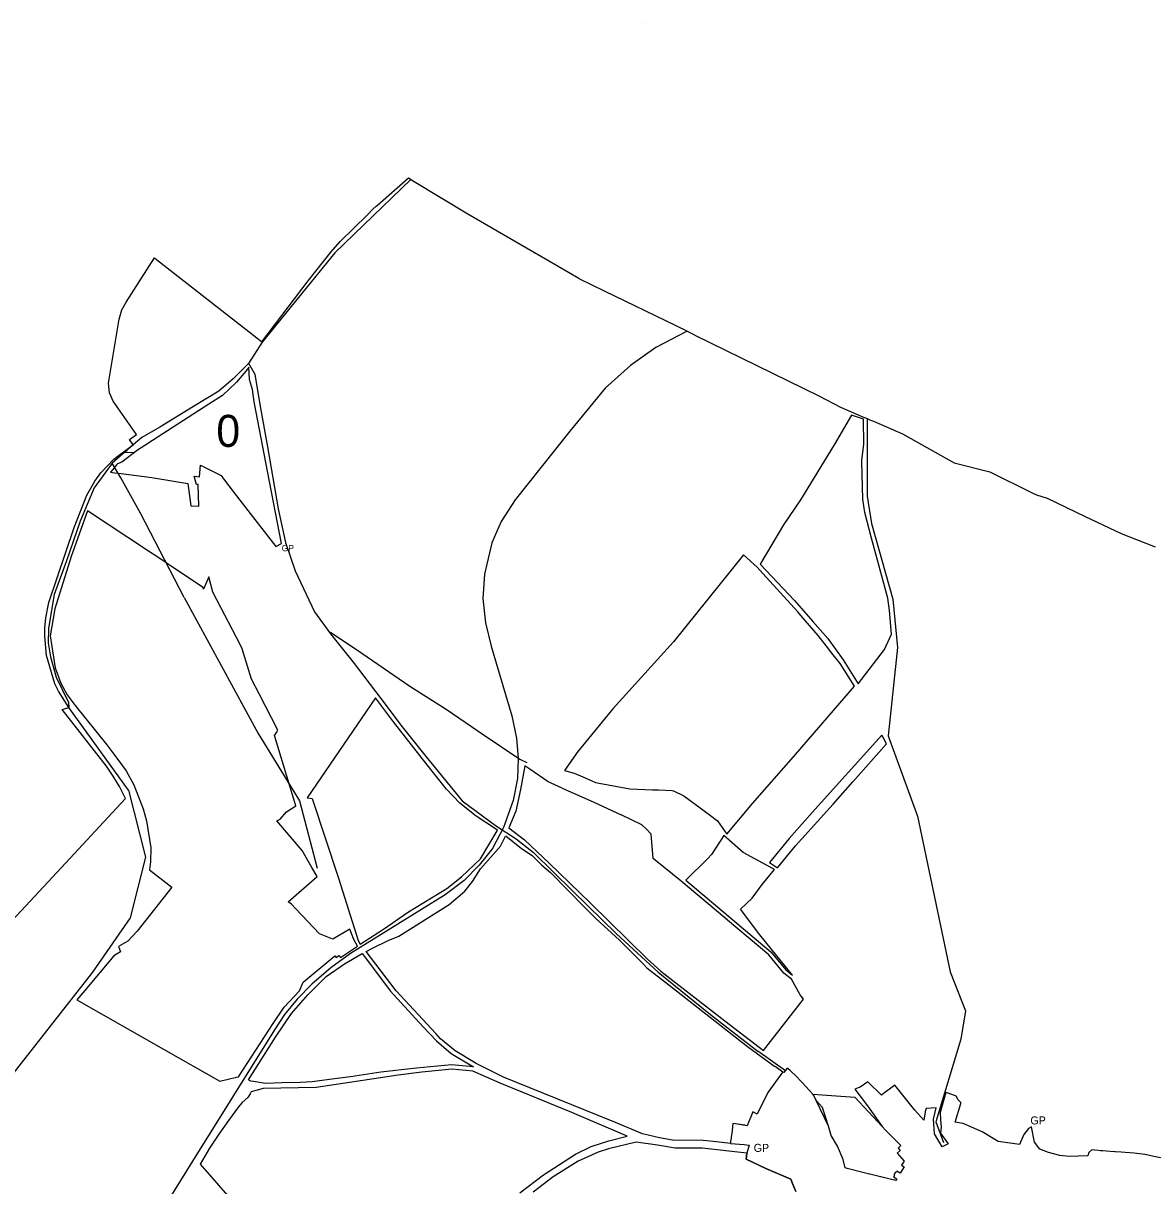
# Model space of a CAD drawing. Extents: x -584576 to -579722, y -1113169 to -1110375.
# Drawn here: x -583298 to -581887, y -1111827 to -1110375 of the extents above; entities that cross this region are included whole.
import ezdxf

# ---------------------------------------------------------------- set-up
doc = ezdxf.new("R2010")
doc.units = 0
for name, color, linetype in [('CESTY', 7, 'Continuous'), ('GRA_ZV', 7, 'Continuous'), ('Level 255', 7, 'Continuous'), ('OVNE_PRE', 7, 'Continuous'), ('OVNE_SET', 7, 'Continuous'), ('OVNI_PRE', 7, 'Continuous'), ('OVNI_SET', 7, 'Continuous'), ('VODA', 7, 'Continuous')]:
    doc.layers.add(name, color=color, linetype=linetype)

msp = doc.modelspace()

# ---------------------------------------------------------------- linework, layer by layer
at = {"layer": 'CESTY'}
for points in [[(-582468.3, -1110759.2), (-582507.4, -1110779.5), (-582539, -1110802), (-582570.7, -1110830.3), (-582614.7, -1110884.3), (-582683, -1110970.1), (-582700.7, -1110997.1), (-582712.1, -1111023.6), (-582721.3, -1111062.9), (-582723.5, -1111093.1), (-582720.2, -1111123.6), (-582713.1, -1111152.8), (-582687.2, -1111239.6), (-582681.3, -1111267.8), (-582679.5, -1111293.2), (-582680.3, -1111317.9), (-582685.6, -1111345.4), (-582697.6, -1111379.3), (-582711.3, -1111405.4), (-582728.2, -1111426.4), (-582746.7, -1111445.5), (-582770.6, -1111463.3), (-582888.9, -1111536.8), (-582913.6, -1111554.6), (-582937.2, -1111574.8), (-582955.7, -1111593.9), (-582971.4, -1111612.9), (-582984, -1111632), (-583086.3, -1111796.1), (-583161.2, -1111917)], [(-582243.2, -1110869.4), (-582243.2, -1110965.4), (-582238, -1110999.4), (-582211.4, -1111094), (-582205.5, -1111154.6), (-582217.3, -1111264.7), (-582180.4, -1111365.1), (-582139.7, -1111559.5), (-582120.5, -1111608.2), (-582126.4, -1111643.7), (-582157.5, -1111747.1), (-582147.9, -1111773)]]:
    msp.add_lwpolyline(points, dxfattribs=at)
at = {"layer": 'GRA_ZV'}
for p, q in [((-582691, -1111379.9), (-582691, -1111379.9)), ((-582220.5, -1111757.3), (-582220.5, -1111757.3))]:
    msp.add_line(p, q, dxfattribs=at)
for points in [[(-582262.9, -1110864), (-582284.5, -1110901.4), (-582326.8, -1110969.9), (-582347.8, -1111001.1), (-582377.1, -1111050.1), (-582334, -1111095.7), (-582311.3, -1111122), (-582292.7, -1111143.1), (-582273.4, -1111169.8), (-582254.7, -1111199.8), (-582221.7, -1111156.7), (-582213, -1111137.6), (-582215.4, -1111108.3), (-582217.5, -1111092.7), (-582238.1, -1111018), (-582246.4, -1110985.6), (-582248.6, -1110969.1), (-582250, -1110922.9), (-582250.1, -1110920.3), (-582247.4, -1110901), (-582247.9, -1110869.3), (-582262.9, -1110864)], [(-582958.5, -1111348.1), (-582964.3, -1111328.7), (-582983.7, -1111264.3), (-582981.5, -1111260.6), (-582979.5, -1111257.8), (-583002.9, -1111212.2), (-583012.5, -1111194), (-583024.1, -1111156), (-583026.2, -1111151.6), (-583060.7, -1111085.4), (-583065.7, -1111066.3), (-583072.4, -1111081.5), (-583072.8, -1111079.4), (-583117.4, -1111049.8), (-583118.3, -1111049.2), (-583128, -1111042.9), (-583128.5, -1111042.5), (-583141.4, -1111034.1), (-583217.5, -1110983.8), (-583235.9, -1111035), (-583238, -1111040.7), (-583258.3, -1111106.2), (-583263.9, -1111139.9), (-583258, -1111179.7), (-583250.7, -1111198.8), (-583242.7, -1111213.7), (-583233, -1111227), (-583193.1, -1111275.8), (-583180.6, -1111292.7), (-583169, -1111308.5), (-583159.7, -1111326.1), (-583147.8, -1111356.1), (-583143.8, -1111370.8), (-583138.5, -1111404.8), (-583138.9, -1111422), (-583140, -1111432), (-583112.2, -1111453.8)], [(-582398, -1111038.6), (-582485.4, -1111147.4), (-582561.3, -1111231.2), (-582605, -1111284.3), (-582621.6, -1111307.9), (-582609.4, -1111311.3), (-582598.8, -1111316), (-582588.3, -1111320.5), (-582582.7, -1111323.1), (-582540, -1111330.9), (-582511.6, -1111332.1), (-582504.2, -1111332.4), (-582486.8, -1111332.9), (-582485.4, -1111333.6), (-582472.4, -1111339.8), (-582452.2, -1111354.9), (-582445.4, -1111359.7), (-582439.2, -1111364.4), (-582430.5, -1111371.1), (-582418.5, -1111387.4), (-582386.6, -1111349.1), (-582335.5, -1111291.1), (-582259, -1111202.6), (-582277.1, -1111174.2), (-582287.4, -1111161.4), (-582294, -1111152.8), (-582304.7, -1111139.6), (-582315.5, -1111126.9), (-582326.2, -1111114.3), (-582330.2, -1111109.8), (-582373.8, -1111062), (-582380.6, -1111053.9), (-582398, -1111038.6)], [(-582705.4, -1111382.6), (-582731.7, -1111365.1), (-582752.1, -1111348.7), (-582768.8, -1111331.4), (-582783.3, -1111312.9), (-582794.7, -1111298.9), (-582835.1, -1111247.3), (-582857.7, -1111217.2), (-582942.9, -1111342.3), (-582936.7, -1111342.9), (-582903.9, -1111442.7), (-582879.1, -1111520.3), (-582876.8, -1111525.1), (-582847.7, -1111506.2), (-582816.3, -1111484.7), (-582768.5, -1111455.5), (-582750.1, -1111441.1), (-582726.4, -1111418.6), (-582705.7, -1111383.3), (-582705.4, -1111382.6)], [(-582365.5, -1111423), (-582355.2, -1111429.6), (-582332.8, -1111402.1), (-582285.7, -1111350.2), (-582261.3, -1111322.1), (-582219.4, -1111274.8), (-582224, -1111266.1), (-582225.1, -1111264.1), (-582312.2, -1111360.7), (-582340.8, -1111393), (-582365.5, -1111423)], [(-582664.9, -1111306.5), (-582671, -1111302.3), (-582676.6, -1111332)], [(-582624.4, -1111330), (-582638.2, -1111324), (-582641.9, -1111322.4), (-582664.9, -1111306.5)], [(-582676.6, -1111332), (-582682.3, -1111358.7), (-582691, -1111379.9)], [(-582624.4, -1111330), (-582585.6, -1111347.2), (-582550.7, -1111363.4)], [(-582980.9, -1111370.9), (-582976.8, -1111368.9), (-582969, -1111359.8), (-582957.2, -1111352.4), (-582958.5, -1111348.1)], [(-582880.2, -1111527.4), (-582884.9, -1111519), (-582889.5, -1111506.4), (-582910.9, -1111518.8), (-582927.8, -1111512), (-582957.3, -1111480.7), (-582962.5, -1111475.1), (-582966.8, -1111472.1), (-582930.4, -1111440.5), (-582937.2, -1111429.1), (-582949.2, -1111408.2), (-582980.9, -1111370.9)], [(-582517.8, -1111543.8), (-582501.1, -1111558.6), (-582482.3, -1111573.2), (-582421.2, -1111620.6), (-582373, -1111658), (-582323.1, -1111593.7), (-582327, -1111588.5), (-582338, -1111568.8), (-582347.5, -1111561.4), (-582366.4, -1111538.4), (-582417.8, -1111495), (-582421.1, -1111492.2), (-582475.9, -1111446.2), (-582508.1, -1111419.9), (-582510.6, -1111418), (-582513.2, -1111387.5), (-582519.2, -1111381.5), (-582524.9, -1111375.8), (-582550.7, -1111363.4)], [(-582502.8, -1111767.1), (-582524.1, -1111761.9), (-582557.6, -1111747.8), (-582579.6, -1111738.9), (-582697.8, -1111691.3), (-582731.9, -1111674.2), (-582758, -1111658.3), (-582776.3, -1111643.1), (-582782.3, -1111636.5), (-582831.9, -1111583.3), (-582869.2, -1111534.1), (-582868.6, -1111533.8), (-582861.4, -1111530.1), (-582842, -1111520.3), (-582828.5, -1111514.9), (-582765.6, -1111475.5), (-582746.2, -1111459), (-582736.5, -1111446.8), (-582726.5, -1111430.8), (-582701.6, -1111402.4), (-582695.1, -1111389.9)], [(-582694.9, -1111389.6), (-582675.1, -1111405.6), (-582661.7, -1111414.4), (-582649.8, -1111426.5), (-582639.2, -1111435.7), (-582596, -1111479.1), (-582582.3, -1111493), (-582552.8, -1111520.2), (-582523.3, -1111549.7), (-582518.5, -1111554.4), (-582491.3, -1111575.9), (-582439.1, -1111616.8), (-582392.9, -1111652.9), (-582358.7, -1111677.9), (-582358.5, -1111677.6), (-582348.9, -1111684.4)], [(-582691, -1111379.9), (-582671.5, -1111394.5), (-582640.5, -1111424), (-582589.5, -1111473.4), (-582517.8, -1111543.8)], [(-582470.1, -1111445.2), (-582363.2, -1111535.1), (-582344.8, -1111556.9), (-582336.6, -1111563.9), (-582377.5, -1111513.4), (-582401.5, -1111481.4), (-582387.2, -1111467.5), (-582374.4, -1111450.6), (-582359.1, -1111431.7), (-582369, -1111426.4), (-582398.2, -1111410.4), (-582422.5, -1111389.2), (-582437.9, -1111413.2), (-582442.5, -1111417.8), (-582470.1, -1111445.2)], [(-583112.2, -1111453.8), (-583155.2, -1111508.6), (-583167.2, -1111521.2), (-583178.9, -1111527.9), (-583176.3, -1111534.8), (-583184.4, -1111539.5), (-583220.9, -1111582.8), (-583230.9, -1111594.6), (-583227.8, -1111596.2), (-583122.5, -1111656.4), (-583052, -1111696.1), (-583031.4, -1111691), (-583028.7, -1111690.7), (-582985.5, -1111624.1), (-582971.9, -1111603.8), (-582952.4, -1111583.2), (-582948.2, -1111572.7), (-582908.6, -1111539.5), (-582906.8, -1111541.8), (-582903.5, -1111539.1), (-582901.5, -1111541.6), (-582880.2, -1111527.4)], [(-582735.3, -1111678.4), (-582762.8, -1111675.6), (-582806.5, -1111679.8), (-582850.9, -1111685.1), (-582888.9, -1111690.6), (-582908.7, -1111693.4), (-582936.8, -1111697.1), (-582951.9, -1111697.9), (-582974.7, -1111698.4), (-582995, -1111699), (-583010.2, -1111696.8), (-583013.4, -1111696.1), (-583015.1, -1111695.2), (-583016.3, -1111694.4), (-582982.5, -1111641.3), (-582962.6, -1111611.6), (-582942.3, -1111588.2), (-582919.3, -1111565.6), (-582896.3, -1111549.8), (-582874.3, -1111536.7), (-582872.8, -1111538.7), (-582839.1, -1111583.5), (-582798.4, -1111627.7), (-582781.4, -1111645.8), (-582763.1, -1111661.6), (-582735.3, -1111678.4)], [(-582701.8, -1111698.6), (-582735.9, -1111683.8), (-582762.2, -1111681.1), (-582799.6, -1111684.8), (-582829.4, -1111688.6), (-582873.5, -1111695.3), (-582931.9, -1111704.1), (-582997.9, -1111705.4)], [(-582348.9, -1111684.4), (-582367.6, -1111710.5), (-582380.9, -1111737.2), (-582386.2, -1111734.5), (-582393.4, -1111751.8)], [(-582997.9, -1111705.4), (-583013, -1111709.3), (-583014.1, -1111711.9), (-583017.3, -1111716.7), (-583024.3, -1111722.8), (-583028.7, -1111728.4), (-583041.2, -1111745.2), (-583053.3, -1111762.4), (-583064.9, -1111779.8), (-583076.7, -1111799.7), (-582959.4, -1111934.2)], [(-582677.4, -1111835.6), (-582647.7, -1111813), (-582607.9, -1111787.3), (-582588.1, -1111777.8), (-582566, -1111770.6), (-582543.2, -1111764.9), (-582612.3, -1111735.2), (-582701.8, -1111698.6)], [(-582311.4, -1111712.3), (-582258.8, -1111716), (-582224.6, -1111752.7)], [(-582224.6, -1111752.7), (-582220.5, -1111757.3), (-582201.5, -1111776.6), (-582204.7, -1111779.7), (-582202, -1111782.7), (-582206, -1111786.3), (-582197.1, -1111796), (-582200.5, -1111801.3), (-582197.2, -1111803.4), (-582202.1, -1111811.3), (-582206.2, -1111808.7), (-582207.1, -1111810.3), (-582207.8, -1111809.9), (-582209.9, -1111813.3), (-582209.2, -1111813.7), (-582210.3, -1111815.5), (-582206.3, -1111818), (-582207.7, -1111820.4), (-582247, -1111810.6), (-582268.4, -1111805.3), (-582271, -1111804.5), (-582273.3, -1111794), (-582280.5, -1111777.2), (-582288.4, -1111764), (-582291.8, -1111752.5), (-582299, -1111728.9), (-582307, -1111720.2), (-582310, -1111714), (-582311.4, -1111712.3)], [(-582411, -1111748.9), (-582411.5, -1111752.9), (-582412.2, -1111758.2), (-582413.4, -1111766.7), (-582414, -1111772), (-582414.3, -1111773.9), (-582431.5, -1111771.8), (-582448.2, -1111770.4), (-582486.7, -1111769.7), (-582502.8, -1111767.1)], [(-582393.4, -1111751.8), (-582408, -1111749.4), (-582411, -1111748.9)], [(-582449.4, -1111779.8), (-582483.4, -1111780), (-582505.2, -1111776.2), (-582532.1, -1111772.3), (-582566.4, -1111780.7), (-582579.4, -1111784.7), (-582604.3, -1111796.3), (-582635.5, -1111815.8), (-582660.5, -1111834.8)], [(-582332.6, -1111834.1), (-582336.5, -1111824), (-582338.7, -1111818.5), (-582369.8, -1111805.2), (-582394.5, -1111793.8), (-582393.9, -1111786), (-582449.4, -1111779.8)]]:
    msp.add_lwpolyline(points, dxfattribs=at)
at = {"layer": 'Level 255'}
msp.add_line((-582660.9, -1110659.8), (-582655.3, -1110663.1), dxfattribs=at)
at = {"layer": 'OVNE_PRE'}
for p, q in [((-582816.5, -1110567.7), (-582809.2, -1110572.3)), ((-583006, -1110767.5), (-582999.5, -1110772.4)), ((-582343.4, -1111679.8), (-582343.4, -1111679.8))]:
    msp.add_line(p, q, dxfattribs=at)
for points in [[(-582999.5, -1110772.4), (-582941.9, -1110696.3), (-582913.2, -1110660.1), (-582901.9, -1110647.3), (-582867.5, -1110614), (-582860.9, -1110606.8), (-582856.7, -1110603.2), (-582855.3, -1110601.9), (-582816.5, -1110567.7)], [(-582809.2, -1110572.3), (-582742.4, -1110612.8), (-582660.9, -1110659.8)], [(-583160.2, -1110901.2), (-583164.8, -1110894.4), (-583156.1, -1110888.3), (-583185.2, -1110846.5), (-583190, -1110836.2), (-583191.3, -1110824.3), (-583177.8, -1110744.4), (-583174.4, -1110732.5), (-583169.3, -1110723), (-583133.6, -1110667.7)], [(-582603.6, -1110693.1), (-582602.6, -1110693.7), (-582572.1, -1110708.9)], [(-582572.1, -1110708.9), (-582482.6, -1110752.3), (-582474.1, -1110756.3), (-582473.6, -1110756.5), (-582467.5, -1110759.6), (-582459.3, -1110763.8), (-582458.5, -1110764.2), (-582303.6, -1110840.2), (-582276.6, -1110854.2), (-582248, -1110866.5), (-582244.3, -1110868.1), (-582239.3, -1110870.2), (-582235.6, -1110871.8), (-582199.3, -1110887.4), (-582134.7, -1110923.9), (-582090.1, -1110935.1), (-582036.6, -1110961.5), (-582031.9, -1110963.8), (-582018.6, -1110967.9), (-581971.2, -1110990.8), (-581926, -1111011.8), (-581883.7, -1111028.7)], [(-583011.3, -1110832.1), (-583015, -1110819.4), (-583015.9, -1110804.3)], [(-583240.6, -1111229.4), (-583253.6, -1111208.8), (-583258.1, -1111199.9), (-583268.7, -1111164.4), (-583270.8, -1111140.4), (-583270.6, -1111130.1), (-583269.5, -1111117.2), (-583265.8, -1111098.3), (-583234.2, -1111004.5), (-583218.1, -1110963.9), (-583208.4, -1110946.5), (-583200.8, -1110936.4), (-583184.6, -1110919.1), (-583177.3, -1110913.7), (-583160.2, -1110901.2)], [(-583180.9, -1111322.5), (-583185.4, -1111315.2), (-583193.9, -1111302.8), (-583248.9, -1111231.7), (-583240.6, -1111229.4)], [(-583170.1, -1111343.2), (-583170.8, -1111341.4), (-583177.5, -1111328), (-583178.8, -1111325.9), (-583180.9, -1111322.5)], [(-583891.8, -1112051.5), (-583740.7, -1111942.5), (-583688.5, -1111904.6), (-583675.7, -1111894.8), (-583666.2, -1111885.1), (-583600.7, -1111808.6), (-583566.2, -1111771.3), (-583537.4, -1111740.1), (-583451.5, -1111647.2), (-583441.4, -1111636.3), (-583367.8, -1111556.5), (-583325, -1111510.2), (-583316.9, -1111501.4), (-583239, -1111417.4), (-583191.9, -1111366.6), (-583170.1, -1111343.2)]]:
    msp.add_lwpolyline(points, dxfattribs=at)
at = {"layer": 'OVNE_SET'}
for p, q in [((-583009.1, -1110847.4), (-583011.3, -1110832.1)), ((-582252.3, -1111703.6), (-582252.3, -1111703.6))]:
    msp.add_line(p, q, dxfattribs=at)
for points in [[(-582660.9, -1110659.8), (-582657.9, -1110661.6), (-582655.3, -1110663.1), (-582603.6, -1110693.1)], [(-583133.6, -1110667.7), (-583131.4, -1110669.5), (-583006, -1110767.5)], [(-583015.9, -1110804.3), (-583017.7, -1110806.7), (-583031.4, -1110823.1), (-583048.7, -1110839.7), (-583065.9, -1110850.6), (-583136.1, -1110896), (-583145.8, -1110902), (-583155, -1110907.9), (-583174.7, -1110923), (-583179.8, -1110924.8), (-583181.1, -1110926.3), (-583185.7, -1110931.9), (-583188.6, -1110935.3)], [(-583188.6, -1110935.3), (-583183.6, -1110936), (-583175.5, -1110937.1), (-583137.1, -1110942), (-583092.1, -1110949.6), (-583088.2, -1110977.6), (-583078.3, -1110977.9), (-583079.1, -1110950.9), (-583081.3, -1110950.7), (-583084.2, -1110940.5), (-583077.5, -1110941.1), (-583076.1, -1110926.8), (-583050.5, -1110939.7), (-583047.7, -1110943.6), (-583034.2, -1110961), (-583014.2, -1110986.9), (-582982.2, -1111028.1), (-582974.9, -1111024.4), (-582990, -1110947.1), (-583009.1, -1110847.4)]]:
    msp.add_lwpolyline(points, dxfattribs=at)
at = {"layer": 'OVNI_PRE'}
for p, q in [((-582413.4, -1111766.7), (-582414, -1111772)), ((-582412.2, -1111758.2), (-582413.4, -1111766.7)), ((-581954.6, -1111783), (-581959, -1111782.4)), ((-581896.6, -1111787.7), (-581909.7, -1111786.2)), ((-582202.1, -1111811.3), (-582206.2, -1111808.7))]:
    msp.add_line(p, q, dxfattribs=at)
for points in [[(-582343.4, -1111679.8), (-582347.6, -1111685.4), (-582348.3, -1111684.9)], [(-582339.6, -1111682.7), (-582340.1, -1111682.3), (-582343.4, -1111679.8)], [(-582201.5, -1111776.6), (-582204.7, -1111779.7), (-582202, -1111782.7), (-582206, -1111786.3), (-582197.1, -1111796), (-582200.5, -1111801.3)], [(-581870.1, -1111793.2), (-581883.1, -1111790.6), (-581896.6, -1111787.7)], [(-582200.5, -1111801.3), (-582197.2, -1111803.4), (-582202.1, -1111811.3)]]:
    msp.add_lwpolyline(points, dxfattribs=at)
at = {"layer": 'OVNI_SET'}
for p, q in [((-582348.9, -1111684.4), (-582367.6, -1111710.5)), ((-582348.3, -1111684.9), (-582348.9, -1111684.4)), ((-582331.3, -1111690.9), (-582339.6, -1111682.7)), ((-582315.9, -1111707.3), (-582324.5, -1111697.7)), ((-582311.4, -1111712.3), (-582315.9, -1111707.3)), ((-582254.7, -1111704.6), (-582258.7, -1111706.2)), ((-582367.6, -1111710.5), (-582380.9, -1111737.2)), ((-582310, -1111714), (-582311.4, -1111712.3)), ((-582307, -1111720.2), (-582310, -1111714)), ((-582291.8, -1111752.5), (-582307, -1111720.2)), ((-582380.9, -1111737.2), (-582386.2, -1111734.5)), ((-582411.5, -1111752.9), (-582412.2, -1111758.2)), ((-582288.4, -1111764), (-582291.8, -1111752.5)), ((-582220.5, -1111757.3), (-582201.5, -1111776.6)), ((-582414, -1111772), (-582414.3, -1111773.9)), ((-582414.3, -1111773.9), (-582397.1, -1111775.5)), ((-581951.8, -1111783.2), (-581954.6, -1111783))]:
    msp.add_line(p, q, dxfattribs=at)
for points in [[(-582324.5, -1111697.7), (-582326.6, -1111695.6), (-582331.3, -1111690.9)], [(-582258.7, -1111706.2), (-582243.1, -1111727.2), (-582224.6, -1111752.7), (-582220.5, -1111757.3)], [(-582225.6, -1111713.8), (-582242.4, -1111697.1), (-582252.3, -1111703.6), (-582254.7, -1111704.6)], [(-582184, -1111732.6), (-582209, -1111701.3), (-582224.9, -1111713.3), (-582225.6, -1111713.8)], [(-582145.2, -1111710.4), (-582152.1, -1111735.3), (-582151.6, -1111744.3)], [(-582132, -1111714.8), (-582133.2, -1111714.3), (-582143.6, -1111710.9), (-582145.2, -1111710.4)], [(-582123.5, -1111749), (-582133.6, -1111747.2), (-582126.2, -1111724.2), (-582126.5, -1111722.9), (-582129.5, -1111719.6), (-582132, -1111714.8)], [(-582386.2, -1111734.5), (-582393.4, -1111751.8), (-582396.4, -1111751.3)], [(-582170.8, -1111734.3), (-582172.5, -1111744.9), (-582184, -1111732.6)], [(-582160.6, -1111743.8), (-582157.1, -1111729.6), (-582169.7, -1111730.4), (-582170, -1111731.4), (-582170.8, -1111734.3)], [(-582396.4, -1111751.3), (-582408, -1111749.4), (-582411, -1111748.9), (-582411.5, -1111752.9)], [(-582142.2, -1111774.6), (-582149.7, -1111778.1), (-582159.3, -1111762.1), (-582160.6, -1111743.8)], [(-582151.6, -1111744.3), (-582151, -1111753.5), (-582151.6, -1111761), (-582142.2, -1111774.6)], [(-582082, -1111770.3), (-582099.9, -1111759.4), (-582123.5, -1111749)], [(-582038.2, -1111753.3), (-582041.8, -1111755.2), (-582047.5, -1111762.9)], [(-582027.5, -1111781.2), (-582034.4, -1111772.5), (-582038.2, -1111753.3)], [(-582268.4, -1111805.3), (-582271, -1111804.5), (-582273.3, -1111794), (-582280.5, -1111777.2), (-582288.4, -1111764)], [(-582047.5, -1111762.9), (-582053.2, -1111775.1), (-582079.6, -1111771.5), (-582082, -1111770.3)], [(-582397.1, -1111775.5), (-582391, -1111776.2), (-582393.9, -1111786)], [(-581966.5, -1111785.1), (-581967.5, -1111789.4), (-581990.9, -1111790.2), (-582002.5, -1111789.2), (-582017, -1111785.2), (-582027.5, -1111781.2)], [(-581959, -1111782.4), (-581962.8, -1111782.1), (-581966.5, -1111785.1)], [(-582393.9, -1111786), (-582394.5, -1111793.8), (-582369.8, -1111805.2)], [(-581926.1, -1111785), (-581933.3, -1111784.5), (-581934.3, -1111784.4), (-581939.7, -1111784.1), (-581944.4, -1111783.7), (-581948.8, -1111783.4), (-581951.8, -1111783.2)], [(-581909.7, -1111786.2), (-581915.1, -1111785.8), (-581921.2, -1111785.4), (-581926.1, -1111785)], [(-582369.8, -1111805.2), (-582338.7, -1111818.5), (-582336.5, -1111824), (-582332.6, -1111834.1)], [(-582206.3, -1111818), (-582207.7, -1111820.4), (-582213, -1111819.1), (-582247, -1111810.6), (-582268.4, -1111805.3)], [(-582206.2, -1111808.7), (-582207.1, -1111810.3), (-582207.8, -1111809.9), (-582209.9, -1111813.3), (-582209.2, -1111813.7), (-582210.3, -1111815.5), (-582206.3, -1111818)]]:
    msp.add_lwpolyline(points, dxfattribs=at)
at = {"layer": 'VODA'}
for p, q in [((-582524.4, -1110374.5), (-582524.4, -1110374.5)), ((-582813, -1110569.5), (-582813, -1110569.5)), ((-583016.2, -1110799.2), (-583014.4, -1110803)), ((-583014.4, -1110803), (-583014.4, -1110803)), ((-583167.4, -1110910.4), (-583167.4, -1110910.4)), ((-583167.4, -1110910.4), (-583167.4, -1110910.4)), ((-583175.9, -1110942.4), (-583186.5, -1110924.3)), ((-583175.9, -1110942.4), (-583175.9, -1110942.4)), ((-583175.9, -1110942.4), (-583175.9, -1110942.4)), ((-583166.3, -1111332.7), (-583240.6, -1111229.4)), ((-582379.9, -1111658.3), (-582345.2, -1111682.7))]:
    msp.add_line(p, q, dxfattribs=at)
for points in [[(-582813, -1110569.5), (-582908.5, -1110661.3), (-582999.4, -1110772.8)], [(-582999.4, -1110772.8), (-583016.4, -1110799.7), (-583035.3, -1110818.6), (-583053.4, -1110834.1), (-583085.2, -1110853.3), (-583126.9, -1110879.2), (-583149.5, -1110892.1)], [(-583016.2, -1110799.2), (-583008.3, -1110813), (-583002, -1110850.7), (-582992.6, -1110903.9), (-582979.1, -1110981.1), (-582970.2, -1111023.2), (-582957.9, -1111058.7), (-582933.8, -1111109.7), (-582913.9, -1111137.4), (-582885.4, -1111172.9), (-582851.1, -1111218.1), (-582824.3, -1111253.4), (-582794.5, -1111291.1), (-582749.4, -1111345.9), (-582706.6, -1111377.7), (-582681.8, -1111393.4), (-582660.2, -1111410.4), (-582611.1, -1111459), (-582556.7, -1111512), (-582504.4, -1111560.2), (-582438.9, -1111613), (-582379.4, -1111659)], [(-583149.5, -1110892.1), (-583160.2, -1110901.2), (-583186.5, -1110924.3), (-583209.1, -1110954.8), (-583226.5, -1110996.4), (-583243.8, -1111046), (-583259.1, -1111088.3), (-583266, -1111130.3), (-583266.4, -1111148.6), (-583263.7, -1111165.9), (-583256.4, -1111191.3), (-583241.2, -1111223.2), (-583240.6, -1111229.4)], [(-583172.6, -1110910.2), (-583167.4, -1110910.4), (-583158.7, -1110910.7)], [(-583096.8, -1111091.8), (-583150.9, -1110987.6), (-583175.9, -1110942.4)], [(-583096.8, -1111091.8), (-583004.4, -1111261.7), (-582952.7, -1111345.9), (-582930.5, -1111430.2)], [(-582913.7, -1111135.2), (-582874.9, -1111161.4), (-582814.7, -1111202.8), (-582769.2, -1111231.6), (-582721.9, -1111264.1), (-582677.2, -1111294), (-582668.7, -1111298.1)], [(-583166.3, -1111332.7), (-583144.8, -1111416.2), (-583164.1, -1111492.3), (-583211.4, -1111560.2), (-583442.7, -1111855), (-583478.9, -1111903.8), (-583547.6, -1111967.3), (-583768.6, -1112166.8), (-583972.6, -1112302), (-584008.1, -1112326.4), (-584045.8, -1112361.1)]]:
    msp.add_lwpolyline(points, dxfattribs=at)

# ---------------------------------------------------------------- texts
at = {"layer": 'Level 255'}
for s, height, p in [('0', 40, (-583056.5, -1110903.8)), ('GP', 7.9, (-582974.8, -1111034.2)), ('GP', 10, (-582039.5, -1111750.2)), ('GP', 10, (-582385.2, -1111784.5))]:
    msp.add_text(s, height=height, dxfattribs=at).set_placement(p)

doc.saveas('drawing.dxf')
